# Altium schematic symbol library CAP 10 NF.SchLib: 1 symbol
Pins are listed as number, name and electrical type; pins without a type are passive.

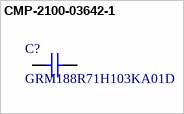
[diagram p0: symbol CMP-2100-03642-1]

## CMP-2100-03642-1
designator C?, comment GRM188R71H103KA01D
Chip Capacitor, 10 nF, +/- 10%, 50 V, -55 to 125 degC, 0603 (1608 Metric), RoHS, Tape and Reel; Manufacturer: Murata; Insulation Resistance: 10GR; Dielectric: X7R; Voltage Rating: 50V; Capacitance: 10nF; Material: Ceramic
footprint CAPC1608X90X35LL10T15
footprint CAPC1608X90X35ML10T15 (Chip Capacitor, 2-Leads, Body 1.7x0.9mm, IPC Low Density)
footprint CAPC1608X90X35NL10T15 (Chip Capacitor, 2-Leads, Body 1.7x0.9mm, IPC Medium Density)
pins: 1, 2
